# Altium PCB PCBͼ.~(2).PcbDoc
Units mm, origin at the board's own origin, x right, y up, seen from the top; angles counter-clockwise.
Board outline 152.4 x 101.6 mm, 2 copper layers (Top Layer, Bottom Layer); 11 components, 8 nets, 24 pads, 0 vias.
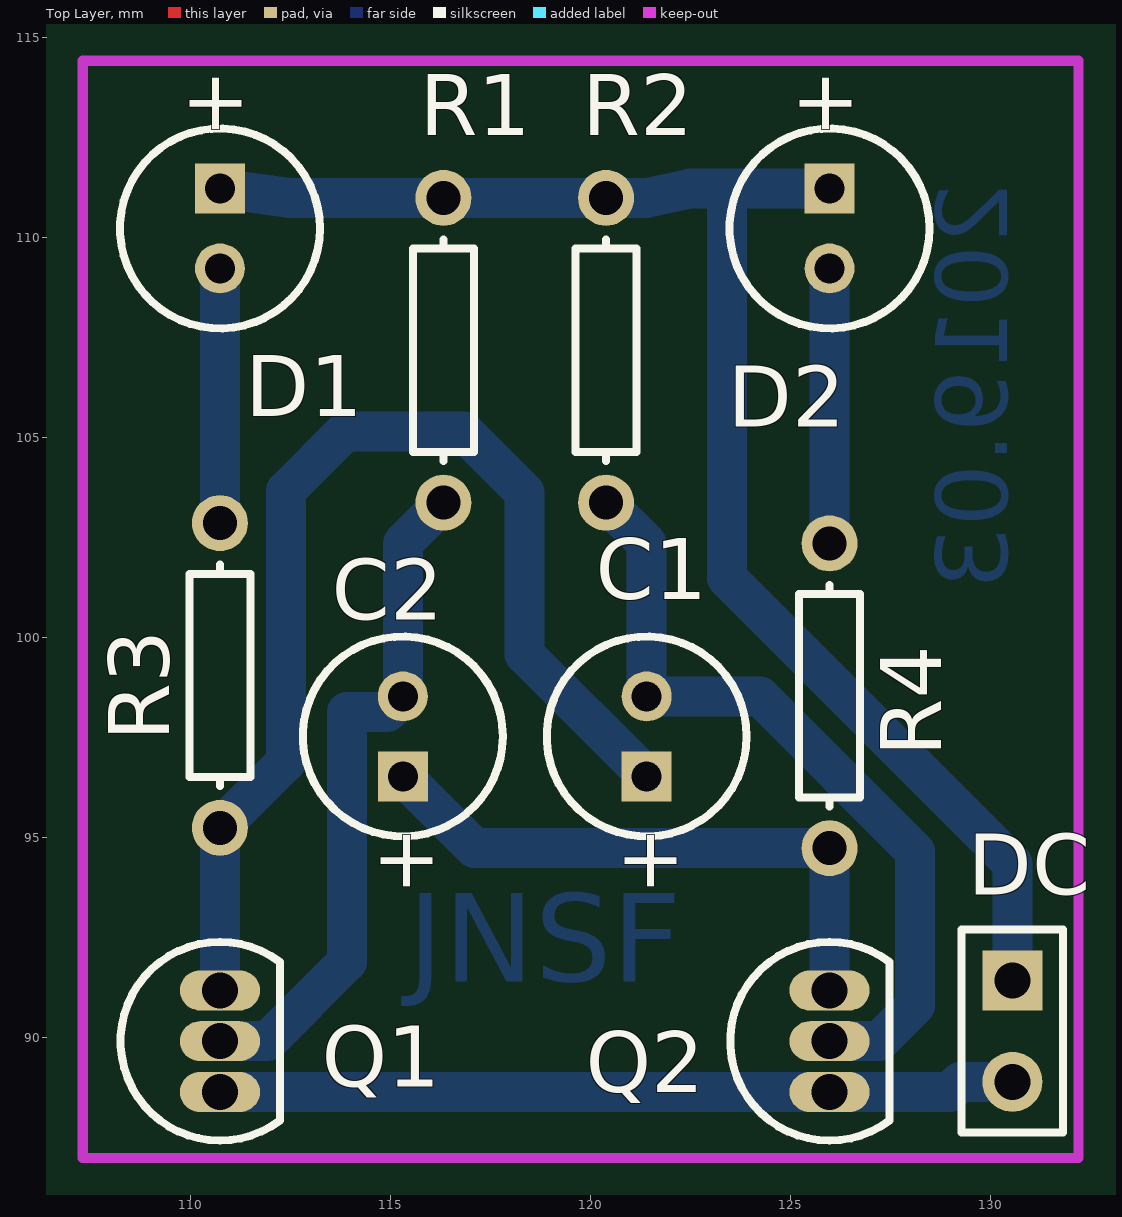
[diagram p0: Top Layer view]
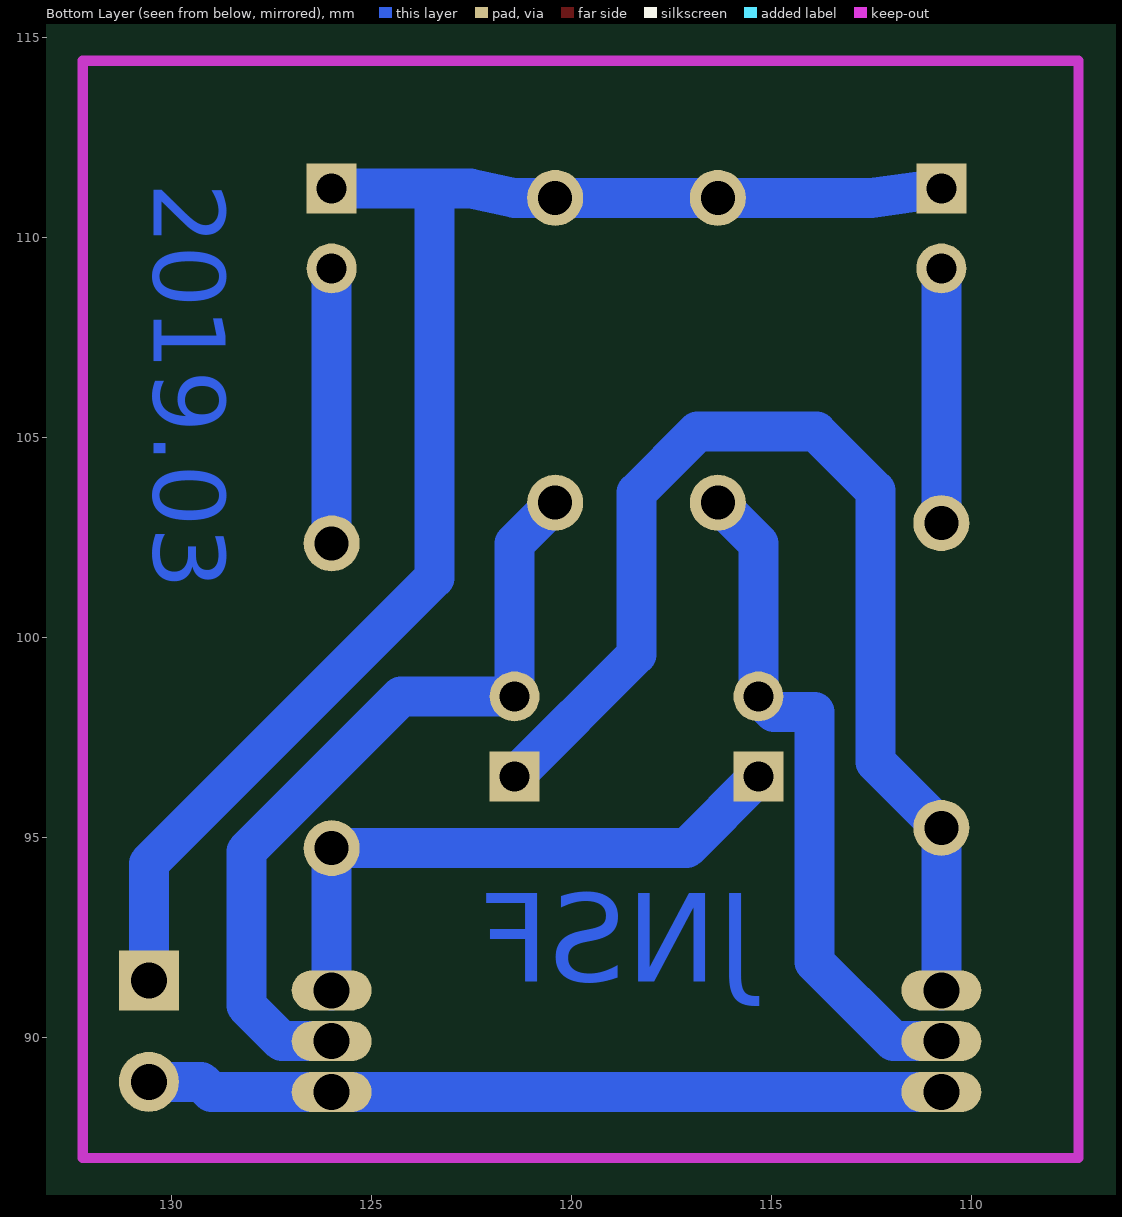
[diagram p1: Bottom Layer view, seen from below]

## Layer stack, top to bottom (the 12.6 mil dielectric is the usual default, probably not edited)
Top Layer: signal copper 0.0356
Dielectric: dielectric 0.32, FR-4, Dk 4.8
Bottom Layer: signal copper 0.0356

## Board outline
25.4,25.4 177.8,25.4 177.8,127 25.4,127

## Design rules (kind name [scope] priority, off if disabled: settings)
Clearance [All] p1: gap=0.254
PolygonConnect [All] p1: connectstyle=Relief reliefconductorwidth=0.254 reliefentries=4 polygonreliefangle="90 Angle"
RoutingLayers [All] p1: top layer_v5=FALSE bottom layer_v5=TRUE
RoutingVias [All] p1: holewidth=0.711 width=1.27 viastyle="Through Hole" minholewidth=0.711 minwidth=1.27 maxholewidth=0.711 maxwidth=1.27
SilkscreenOverComponentPads [All] p1: minsilkscreentomaskgap=0.254
SolderMaskExpansion [All] p1: expansion=0.102
Width [All] p1: maxlimit=1 minlimit=0.4 preferedwidth=1
26 further rules are at their usual default settings.

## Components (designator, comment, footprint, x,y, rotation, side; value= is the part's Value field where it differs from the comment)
C1 "10U" CAPPR2-5x6.8 121.412,97.536 r90 top
C2 "10U" CAPPR2-5x6.8 115.316,97.536 r90 top
D1 "LED0" CAPPR2-5x6.8 110.744,110.236 r270 top
D2 "LED0" CAPPR2-5x6.8 125.984,110.236 r270 top
DC "3v" HDR1X2 130.556,91.44 r270 top
Q1 "9013" BCY-W3/E4 110.744,89.916 r0 top
Q2 "9013" BCY-W3/E4 125.984,89.916 r0 top
R1 "47K" AXIAL-0.3 116.332,107.188 r90 top
R2 "47K" AXIAL-0.3 120.396,107.188 r90 top
R3 "510" AXIAL-0.3 110.744,99.06 r90 top
R4 "510" AXIAL-0.3 125.984,98.552 r90 top

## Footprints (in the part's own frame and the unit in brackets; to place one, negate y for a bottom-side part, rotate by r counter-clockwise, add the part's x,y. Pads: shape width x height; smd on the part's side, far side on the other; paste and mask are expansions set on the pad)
AXIAL-0.3 [mm] "Axial Device, Thru-Hole; 2 Leads; 0.3 in Pin Spacing"
  round 1.4 hole 0.85: 1(-3.81,0) 2(3.81,0)
  silkscreen extent -2.77,-0.76 2.77,0.76
BCY-W3/E4 [mm] "TO, Flat Index; 3 In-Line, Axial Leads; Body Dia. 4.5mm; Leads 0.51 x 0.48 mm (max)"
  oval 2x1 hole 0.9: 1(0,-1.27) 2(0,0) 3(0,1.27)
  silkscreen extent -2.48,-2.48 1.5,2.48
CAPPR2-5x6.8 [mm] "Capacitor, Electrolytic, Radial; Body 5 x 6.8 mm (Dia.xH typ); Pin Spacing 2 mm (typ)"
  rect 1.25x1.25 hole 0.75: 1(-1,0)
  round 1.25 hole 0.75: 2(1,0)
  silkscreen extent -2.5,-2.5 2.5,2.5
HDR1X2 [mm] "Connector; Header; 2 Position"
  rect 1.5x1.5 hole 0.9: 1(0,0)
  round 1.5 hole 0.9: 2(2.54,0)
  silkscreen extent -1.27,-1.27 3.81,1.27

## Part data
C1 C2: library part "Cap Pol2", "Polarized Capacitor (Axial)"
D1 D2: "Typical INFRARED GaAs LED"
DC: library part "Header 2", "Header, 2-Pin"
Q1 Q2: library part 2N3904, "NPN General Purpose Amplifier"
R1 R2 R3 R4: library part Res1, "Resistor"

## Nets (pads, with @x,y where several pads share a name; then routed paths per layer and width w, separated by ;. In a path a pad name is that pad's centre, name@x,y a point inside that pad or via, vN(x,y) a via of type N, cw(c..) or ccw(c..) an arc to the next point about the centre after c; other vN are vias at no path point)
GND: DC.2 Q1.1 Q2.1 | length 19.9
  Bottom Layer w1: Q1.1 Q2.1 128.992,88.646 129.246,88.9 DC.2
NetC1_1: C1.1 Q1.3 R3.1 | length 28.7
  Bottom Layer w1: Q1.3 R3.1 112.395,96.901 112.395,103.683 113.868,105.156 116.84,105.156 118.364,103.632 118.364,99.584 C1.1
NetC1_2: C1.2 Q2.2 R2.1 | length 19.9
  Bottom Layer w1: R2.1 121.412,102.362 C1.2 124.246,98.536 128.118,94.665 128.118,90.805 127.229,89.916 Q2.2
NetC2_1: C2.1 Q2.3 R4.1 | length 15
  Bottom Layer w1: C2.1 117.11,94.742 R4.1 Q2.3
NetC2_2: C2.2 Q1.2 R1.1 | length 17.1
  Bottom Layer w1: Q1.2 111.938,89.916 113.919,91.897 113.919,98.146 114.926,98.146 C2.2 115.316,102.362 R1.1
NetD1_2: D1.2 R3.2 | length 6.4
  Bottom Layer w1: R3.2 D1.2
NetD2_2: D2.2 R4.2 | length 6.9
  Bottom Layer w1: R4.2 D2.2
VCC: D1.1 D2.1 DC.1 R1.2 R2.2 | length 37.8
  Bottom Layer w1: D1.1 112.487,110.998 115.316,110.998 121.412,110.998 122.514,111.236 D2.1 ; 123.419,110.998 123.419,101.498 130.556,94.361 DC.1

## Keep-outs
Keep-Out Layer:
  lines w0.254: 107.315,86.995 132.207,86.995 132.207,114.427 107.315,114.427 107.315,86.995

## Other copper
Bottom Layer:
  text "2019.03" at 130.429,111.379 h1.8 r90
  text "JNSF" at 115.443,90.678 h3.8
